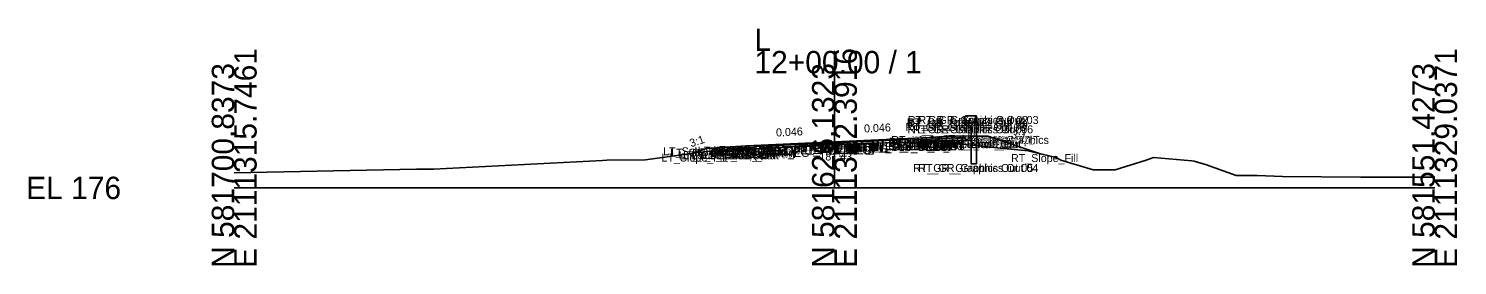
# Model space of a CAD drawing. Extents: x -486 to 1153, y -333 to 9539.
# Drawn here: x -25.7 to 152.8, y 1490.3 to 1519.9 of the extents above; entities that cross this region are included whole.
import ezdxf

# ---------------------------------------------------------------- set-up
doc = ezdxf.new("R2010")
doc.units = 0
for name, color, linetype in [('Default', 7, 'Continuous'), ('Exist CMT Pavement', 7, 'Continuous'), ('Exist Cross Section Cell', 7, 'Continuous'), ('Exist XS Ground Line', 7, 'Continuous'), ('Prop CMT Guardrail Graphics', 7, 'Continuous'), ('Prop CMT Pvmt Course 1', 7, 'Continuous'), ('Prop CMT Pvmt Course 1 Wedge', 7, 'Continuous'), ('Prop CMT Pvmt Course 2', 7, 'Continuous'), ('Prop CMT Pvmt Course 3', 7, 'Continuous'), ('Prop CMT Pvmt Surface', 7, 'Continuous'), ('Prop CMT Pvmt Surface Shoulder', 7, 'Continuous'), ('Prop CMT Pvmt Wedge Surface 1', 7, 'Continuous'), ('Prop CMT Pvmt Wedge Surface 2', 7, 'Continuous'), ('Prop CMT Pvmt Wedge Surface 3', 7, 'Continuous'), ('Prop CMT Shld Paved Course 1', 7, 'Continuous'), ('Prop CMT Shld Paved Course 2', 7, 'Continuous'), ('Prop CMT Shld Paved Course 3', 7, 'Continuous'), ('Prop CMT Slope Grass', 7, 'Continuous'), ('Prop CMT Subgrade Earthwork', 7, 'Continuous'), ('Prop XS Earthwork Shape', 7, 'Continuous'), ('Prop XS SE Text', 7, 'Continuous'), ('Prop XS Side Slope Text', 7, 'Continuous'), ('Scratch_Level_0', 7, 'Continuous'), ('Scratch_Level_1', 7, 'Continuous'), ('Scratch_Level_2', 7, 'Continuous')]:
    doc.layers.add(name, color=color, linetype=linetype)

msp = doc.modelspace()

# ---------------------------------------------------------------- linework, layer by layer
at = {"layer": 'Exist CMT Pavement'}
msp.add_lwpolyline([(75, 1505.43), (84.26, 1505.71)], dxfattribs=at)
at = {"layer": 'Exist Cross Section Cell'}
for p, q in [((75, 1500), (75, 1517.12)), ((0, 1500), (75, 1500)), ((75, 1500), (150, 1500))]:
    msp.add_line(p, q, dxfattribs=at)
at = {"layer": 'Exist XS Ground Line'}
for p, q in [((65.01, 1504.88), (73.51, 1505.37)), ((73.51, 1505.37), (74.35, 1505.41)), ((74.35, 1505.41), (75.23, 1505.44)), ((75.23, 1505.44), (84.26, 1505.71)), ((84.26, 1505.71), (84.88, 1505.7)), ((84.88, 1505.7), (86.53, 1505.65)), ((86.53, 1505.65), (90.27, 1505.57)), ((90.27, 1505.57), (95.29, 1505.01)), ((24.89, 1502.36), (46.03, 1503.42)), ((46.03, 1503.42), (46.57, 1503.47)), ((46.57, 1503.47), (51.4, 1503.51)), ((51.4, 1503.51), (58.94, 1504.55)), ((58.94, 1504.55), (65.01, 1504.88)), ((95.29, 1505.01), (99.22, 1504.62)), ((99.22, 1504.62), (102.7, 1503.79)), ((102.7, 1503.79), (103.27, 1503.46)), ((103.27, 1503.46), (107.31, 1502.26)), ((110.08, 1502.24), (113.93, 1503.45)), ((113.93, 1503.45), (114.86, 1503.79)), ((114.86, 1503.79), (119.65, 1503.39)), ((119.65, 1503.39), (119.96, 1503.36)), ((119.96, 1503.36), (121.49, 1502.9)), ((0, 1501.9), (22.77, 1502.33)), ((22.77, 1502.33), (24.22, 1502.33)), ((24.22, 1502.33), (24.89, 1502.36)), ((107.31, 1502.26), (108.06, 1502.25)), ((108.06, 1502.25), (110.08, 1502.24)), ((121.49, 1502.9), (125.21, 1501.54)), ((125.21, 1501.54), (127.81, 1501.54)), ((127.81, 1501.54), (130.97, 1501.42)), ((130.97, 1501.42), (140.78, 1501.35)), ((140.78, 1501.35), (150, 1501.34))]:
    msp.add_line(p, q, dxfattribs=at)
at = {"layer": 'Prop CMT Guardrail Graphics'}
for points in [[(92.76, 1508.99), (91.43, 1508.99), (91.16, 1508.7)], [(91.16, 1508.7), (91.43, 1508.4)], [(92.76, 1502.99), (92.76, 1508.99)], [(91.43, 1508.4), (91.16, 1508.11)], [(91.16, 1508.11), (91.43, 1507.82), (92.1, 1507.82)], [(92.1, 1507.82), (92.1, 1502.99)], [(92.1, 1502.99), (92.76, 1502.99)]]:
    msp.add_lwpolyline(points, dxfattribs=at)
at = {"layer": 'Prop CMT Pvmt Course 1'}
for points in [[(75, 1505.75), (64, 1505.24)], [(64, 1505.24), (64, 1505.04)], [(64, 1505.04), (65.01, 1505.08)], [(65.01, 1505.17), (75, 1505.62)], [(65.01, 1505.08), (65.01, 1505.17)], [(75, 1505.75), (86, 1506.26)], [(84.26, 1506.05), (75, 1505.62)], [(86, 1506.05), (84.26, 1505.97)], [(84.26, 1505.97), (84.26, 1506.05)], [(86, 1506.26), (86, 1506.05)]]:
    msp.add_lwpolyline(points, dxfattribs=at)
at = {"layer": 'Prop CMT Pvmt Course 1 Wedge'}
for points in [[(75, 1505.62), (65.01, 1505.17)], [(75, 1505.62), (84.26, 1506.05)]]:
    msp.add_lwpolyline(points, dxfattribs=at)
at = {"layer": 'Prop CMT Pvmt Course 2'}
for points in [[(65.01, 1505.08), (64, 1505.04)], [(64, 1505.04), (64, 1504.7)], [(65.01, 1504.75), (65.01, 1505.08)], [(84.26, 1505.97), (86, 1506.05)], [(84.26, 1505.63), (84.26, 1505.97)], [(86, 1505.71), (84.26, 1505.63)], [(86, 1506.05), (86, 1505.71)], [(64, 1504.7), (65.01, 1504.75)]]:
    msp.add_lwpolyline(points, dxfattribs=at)
at = {"layer": 'Prop CMT Pvmt Course 3'}
for points in [[(84.26, 1505.63), (86, 1505.71)], [(84.26, 1505.63), (84.26, 1505.63)], [(86, 1505.71), (86, 1505.71)], [(65.01, 1504.75), (64, 1504.7)], [(64, 1504.7), (64, 1504.7)], [(65.01, 1504.75), (65.01, 1504.75)]]:
    msp.add_lwpolyline(points, dxfattribs=at)
at = {"layer": 'Prop CMT Pvmt Surface'}
for points in [[(75, 1505.75), (64, 1505.24)], [(75, 1505.75), (86, 1506.26)]]:
    msp.add_lwpolyline(points, dxfattribs=at)
at = {"layer": 'Prop CMT Pvmt Surface Shoulder'}
for points in [[(64, 1505.24), (62, 1505.15)], [(86, 1506.26), (91.06, 1506.49)]]:
    msp.add_lwpolyline(points, dxfattribs=at)
at = {"layer": 'Prop CMT Pvmt Wedge Surface 1'}
for points in [[(64, 1505.04), (64, 1505.24)], [(65.01, 1505.08), (64, 1505.04)], [(75, 1505.62), (65.01, 1505.17)], [(65.01, 1505.17), (65.01, 1505.08)], [(75, 1505.62), (84.26, 1506.05)], [(84.26, 1506.05), (84.26, 1505.97)], [(84.26, 1505.97), (86, 1506.05)], [(86, 1506.05), (86, 1506.26)]]:
    msp.add_lwpolyline(points, dxfattribs=at)
at = {"layer": 'Prop CMT Pvmt Wedge Surface 2'}
for points in [[(64, 1505.04), (64, 1505.24)], [(86, 1506.05), (86, 1506.26)]]:
    msp.add_lwpolyline(points, dxfattribs=at)
at = {"layer": 'Prop CMT Pvmt Wedge Surface 3'}
for points in [[(64, 1504.7), (64, 1505.24)], [(86, 1505.71), (86, 1506.26)]]:
    msp.add_lwpolyline(points, dxfattribs=at)
at = {"layer": 'Prop CMT Shld Paved Course 1'}
for points in [[(64, 1505.24), (62, 1505.15), (61.78, 1504.93)], [(61.78, 1504.93), (64, 1505.04)], [(64, 1505.04), (64, 1505.24)], [(86, 1506.26), (91.06, 1506.49), (91.26, 1506.29)], [(91.26, 1506.29), (86, 1506.05)], [(86, 1506.05), (86, 1506.26)]]:
    msp.add_lwpolyline(points, dxfattribs=at)
at = {"layer": 'Prop CMT Shld Paved Course 2'}
for points in [[(64, 1505.04), (61.78, 1504.93), (61.43, 1504.58)], [(64, 1504.7), (64, 1505.04)], [(86, 1506.05), (91.26, 1506.29), (91.58, 1505.97)], [(86, 1505.71), (86, 1506.05)], [(91.58, 1505.97), (86, 1505.71)], [(61.43, 1504.58), (64, 1504.7)]]:
    msp.add_lwpolyline(points, dxfattribs=at)
at = {"layer": 'Prop CMT Shld Paved Course 3'}
for points in [[(86, 1505.71), (91.58, 1505.97)], [(86, 1505.71), (86, 1505.71)], [(91.58, 1505.97), (91.58, 1505.97), (91.58, 1505.97)], [(64, 1504.7), (61.43, 1504.58)], [(61.43, 1504.58), (61.43, 1504.58), (61.43, 1504.58)], [(64, 1504.7), (64, 1504.7)]]:
    msp.add_lwpolyline(points, dxfattribs=at)
at = {"layer": 'Prop CMT Slope Grass'}
for points in [[(62, 1505.15), (59, 1504.91), (57.16, 1504.3)], [(91.06, 1506.49), (91.16, 1506.49)], [(91.16, 1506.49), (94.16, 1506.45)], [(94.16, 1506.45), (100.88, 1504.23)]]:
    msp.add_lwpolyline(points, dxfattribs=at)
at = {"layer": 'Prop CMT Subgrade Earthwork'}
for points in [[(61.43, 1504.58), (60.95, 1505.07)], [(84.26, 1505.63), (86, 1505.71)], [(84.26, 1505.63), (84.26, 1505.71)], [(86, 1505.71), (91.58, 1505.97)], [(91.58, 1505.97), (92.08, 1506.47)], [(64, 1504.7), (61.43, 1504.58)], [(65.01, 1504.75), (64, 1504.7)], [(65.01, 1504.75), (65.01, 1504.88)]]:
    msp.add_lwpolyline(points, dxfattribs=at)
at = {"layer": 'Prop XS Earthwork Shape'}
for points in [[(57.16, 1504.3), (58.94, 1504.55), (61.34, 1504.68), (60.95, 1505.07), (59, 1504.91)], [(74.35, 1505.41), (75, 1505.43), (65.01, 1504.88), (73.51, 1505.37)], [(84.26, 1505.63), (84.26, 1505.71), (84.88, 1505.7), (85.36, 1505.69)], [(85.36, 1505.69), (86, 1505.71), (91.58, 1505.97), (92.08, 1506.47), (94.16, 1506.45), (100.88, 1504.23), (99.22, 1504.62), (95.29, 1505.01), (90.27, 1505.57), (86.53, 1505.65)], [(64, 1504.7), (61.43, 1504.58), (61.34, 1504.68), (65.01, 1504.88), (65.01, 1504.75)]]:
    msp.add_lwpolyline(points, close=True, dxfattribs=at)
at = {"layer": 'Scratch_Level_1'}
for p, q in [((73.51, 1505.37), (67.81, 1505.04)), ((67.81, 1505.04), (67.81, 1505.29)), ((67.81, 1505.04), (67.81, 1505.27)), ((74.35, 1505.41), (73.51, 1505.37)), ((75.23, 1505.44), (74.35, 1505.41)), ((78.37, 1505.53), (75.23, 1505.44)), ((78.37, 1505.78), (78.37, 1505.53))]:
    msp.add_line(p, q, dxfattribs=at)
for points in [[(67.81, 1505.29), (75, 1505.62)], [(75, 1505.62), (78.37, 1505.78)]]:
    msp.add_lwpolyline(points, dxfattribs=at)
at = {"layer": 'Scratch_Level_2'}
for p, q in [((67.81, 1505.04), (65.01, 1504.88)), ((67.81, 1505.29), (67.81, 1505.04)), ((78.37, 1505.53), (78.37, 1505.78)), ((78.37, 1505.78), (78.37, 1505.53)), ((78.37, 1505.53), (84.26, 1505.71))]:
    msp.add_line(p, q, dxfattribs=at)
for points in [[(65.01, 1505.17), (67.81, 1505.29)], [(65.01, 1504.88), (65.01, 1505.17)], [(84.26, 1506.05), (78.37, 1505.78)], [(84.26, 1505.97), (84.26, 1506.05)], [(84.26, 1505.71), (84.26, 1505.97)]]:
    msp.add_lwpolyline(points, dxfattribs=at)

# ---------------------------------------------------------------- texts
at = {"layer": 'Default'}
for s, height, p in [('181.43', 1, (73.12, 1503.43)), ('-', 0.0001, (0, 1500))]:
    msp.add_text(s, height=height, dxfattribs=at).set_placement(p)
at = {"layer": 'Exist Cross Section Cell'}
for s, p in [('L', (65, 1517.12)), ('12+00.00 / 1', (65, 1514.32)), ('EL 176', (-26, 1498.6))]:
    msp.add_text(s, height=2.8, dxfattribs=at).set_placement(p)
for s, p in [('E 2111315.7461', (2.8, 1490)), ('E 2111322.3916', (77.8, 1490)), ('E 2111329.0371', (152.8, 1490)), ('N 581700.8373', (0, 1490)), ('N 581626.1323', (75, 1490)), ('N 581551.4273', (150, 1490))]:
    msp.add_text(s, height=2.8, rotation=90, dxfattribs=at).set_placement(p)
at = {"layer": 'Prop XS SE Text'}
for p in [(67.72, 1506.42), (78.72, 1506.92)]:
    msp.add_text('0.046', height=1, rotation=2.6337, dxfattribs=at).set_placement(p)
at = {"layer": 'Prop XS Side Slope Text'}
for rotation, p in [(341.7371, (97, 1506.3)), (18.2629, (57.09, 1505.07))]:
    msp.add_text('3:1', height=1, rotation=rotation, dxfattribs=at).set_placement(p)
at = {"layer": 'Scratch_Level_0'}
for s, p in [('RT_GR_Graphics Out 01', (84.05, 1507.7)), ('RT_GR_Graphics Out 02', (84.17, 1507.99)), ('RT_GR_Graphics Out 03', (85.49, 1507.99)), ('RT_GR_Graphics Out 08', (83.87, 1507.11)), ('RT_GR_Graphics Out 07', (84.13, 1506.82)), ('RT_GR_Graphics Out 09', (84.15, 1507.4)), ('RT_GR_Graphics Out 06', (84.81, 1506.82)), ('LT_Sub_Trench_Out_DLT', (53.6, 1504.07)), ('LT_PS1_OEOP', (57.91, 1504.15)), ('LT_PV2_OEOT', (59.75, 1504.04)), ('LT_PV1_OEOT', (59.87, 1504.24)), ('LT_PV2_OEEOP', (60.4, 1504.08)), ('LT_PV1_OEEOP', (60.52, 1504.17)), ('RT_PV_IEEOP_EG', (69.92, 1504.43)), ('LT_PV_IEEOP_EG', (69.98, 1504.43)), ('RT_PV2_IEEOP', (70.71, 1504.54)), ('RT_PV3_IEEOP', (70.71, 1504.21)), ('LT_PV2_IEEOP', (70.77, 1504.54)), ('LT_PV3_IEEOP', (70.77, 1504.21)), ('RT_PV1_IEEOP', (70.83, 1504.62)), ('LT_PV1_IEEOP', (70.89, 1504.62)), ('PV2_PGL', (72.35, 1504.54)), ('PV1_PGL', (72.47, 1504.75)), ('RT_PV_OEEOP_EG', (78.8, 1504.71)), ('RT_Sub Tie Out', (79.36, 1504.71)), ('RT_PV2_OEEOP', (79.6, 1504.97)), ('RT_PV3_OEEOP', (79.6, 1504.63)), ('RT_Sub_OEEOP', (79.62, 1504.63)), ('RT_PV1_OEEOP', (79.72, 1505.05)), ('RT_PV2_OEOT', (81.69, 1505.05)), ('RT_PV3_OEOT', (81.69, 1504.71)), ('RT_Sub_OEOT', (81.71, 1504.71)), ('RT_PV1_OEOT', (81.81, 1505.26)), ('RT_GS_OS_GR_Face_Graphics', (82.1, 1505.49)), ('RT_Sub_Trench_Out_DLT', (84.67, 1505.47)), ('RT_Sub_Trench_Out', (85.63, 1504.97)), ('RT_PS3_Shelf_Out', (86.17, 1504.97)), ('RT_PS1_OEOP', (86.91, 1505.49)), ('RT_PS2_OEOP', (86.99, 1505.29)), ('RT_PS3_OEOP', (87.3, 1504.97)), ('RT_GS_OS_CTL', (89.56, 1505.45)), ('LT_Slope_Fill', (53.39, 1503.3)), ('LT_GS_OS_CTL', (54.46, 1503.91)), ('LT_Sub_Trench_Out', (55.54, 1503.58)), ('LT_PS3_Shelf_Out', (56.09, 1503.58)), ('LT_PS3_OEOP', (57.22, 1503.58)), ('LT_PS2_OEOP', (57.57, 1503.93)), ('LT_PV_OEEOP_EG', (59.61, 1503.88)), ('LT_PV3_OEOT', (59.75, 1503.7)), ('LT_Sub_OEOT', (59.77, 1503.7)), ('LT_Sub Tie Out', (60.16, 1503.88)), ('LT_PV3_OEEOP', (60.4, 1503.75)), ('LT_Sub_OEEOP', (60.42, 1503.75)), ('RT_Slope_Fill', (97.06, 1503.23)), ('RT_GR_Graphics Out 05', (84.82, 1501.99)), ('RT_GR_Graphics Out 04', (85.47, 1501.99))]:
    msp.add_text(s, height=1, dxfattribs=at).set_placement(p)

doc.saveas('drawing.dxf')
